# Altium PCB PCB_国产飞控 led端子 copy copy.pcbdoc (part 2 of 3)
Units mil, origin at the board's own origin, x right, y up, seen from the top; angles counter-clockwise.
Board outline 3467.18 x 2997.13 mil, 4 copper layers (Top Layer, Inner1, Inner2, Bottom Layer), stack 2.757 mil thick; 107 components, 163 nets, 527 pads, 148 vias.
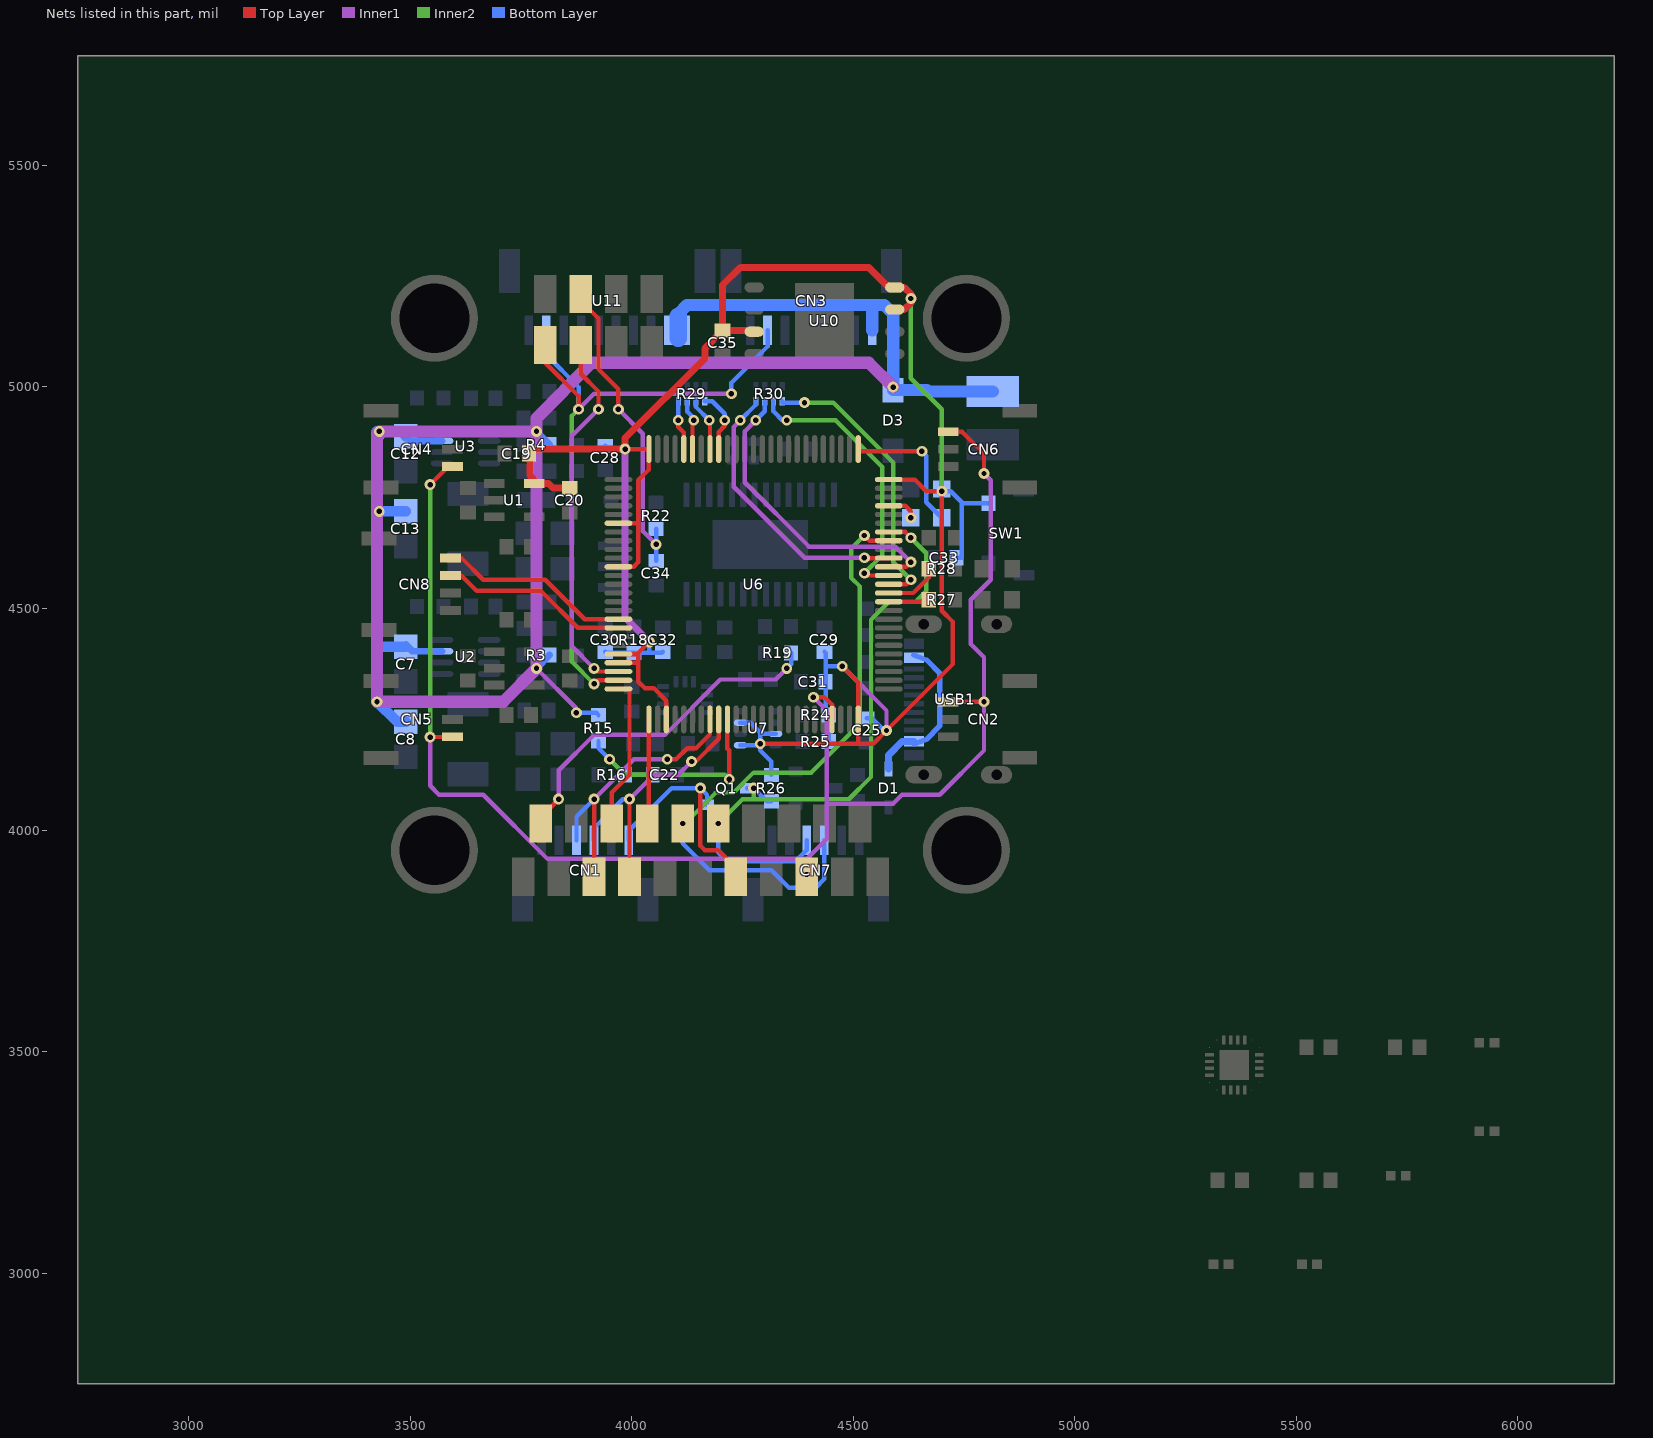
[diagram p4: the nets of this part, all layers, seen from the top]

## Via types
v1: diameter 24.41, hole 12.2, Top Layer to Bottom Layer, 148 vias

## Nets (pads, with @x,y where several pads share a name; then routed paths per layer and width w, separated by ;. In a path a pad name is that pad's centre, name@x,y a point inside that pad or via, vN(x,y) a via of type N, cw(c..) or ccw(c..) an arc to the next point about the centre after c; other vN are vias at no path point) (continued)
LED: CN2.3 CN4.3 CN5.3 CN6.3 pad.5@4395,3894.63 U6.47 | length 3563.7
  Top Layer w10: v1(3545,4209.63) CN5.3@3595.7,4210.23 ; v1(3545,4779.63) 3585.6,4820.23 CN4.3@3595.7,4820.23 ; pad.5@4395,3894.63 v1(4395,3899.63) ; v1(4410,4299.63) 4435,4299.63 4452.2,4282.43 U6.47@4452.17,4249.52 ; CN2.3@4714.29,4289 v1(4795,4289.63) ; CN6.3@4714.29,4899 4745.6,4899.03 4795,4849.63 v1(4795,4804.63)
  Inner1 w10: v1(3545,4209.63) 3545,4099.63 3565,4079.63 3665,4079.63 3810,3934.63 4395,3934.63 ; v1(4410,4299.63) 4440,4269.63 4440,3979.63 4395,3934.63 ; 4440,4059.63 4590,4059.63 4610,4079.63 4695,4079.63 4795,4179.63 v1(4795,4289.63) 4795,4389.63 4765,4419.63 4765,4519.63 4810,4564.63 4810,4789.63 v1(4795,4804.63) ; 4395,3934.63 v1(4395,3899.63) 4395,3934.63
  Inner2 w10: v1(3545,4209.63) v1(3545,4779.63)
LED1: R27.2 U6.61 | length 92
  Top Layer w10: U6.61@4580.1,4515.23 4665.9,4515.23 R27.2@4670.34,4519.63
LED2: R28.2 U6.62 | length 124.4
  Top Layer w10: U6.62@4580.11,4534.94 4635.3,4534.93 4670.3,4569.93 R28.2@4670.34,4589.63
MOTOR1: R29.4 U6.92 | length 142.7
  Top Layer w10: U6.92@4196.26,4859.74 4196.3,4898.33 4210,4912.13 v1(4210,4924.63)
  Bottom Layer w10: R29.4@4164.53,4967.8 4181.8,4967.83 4210,4939.63 v1(4210,4924.63)
MOTOR2: R29.3 U6.93 | length 122.2
  Top Layer w10: v1(4175,4924.63) 4176.6,4924.63 U6.93@4176.57,4859.74
  Bottom Layer w10: R29.3@4144.84,4967.8 4144.8,4954.83 v1(4175,4924.63)
MOTOR3: R29.2 U6.95 | length 117
  Top Layer w10: U6.95@4137.2,4859.74 4137.2,4924.63 v1(4140,4924.63)
  Bottom Layer w10: R29.2@4125.16,4967.8 4125.2,4944.43 4140,4929.63 v1(4140,4924.63)
MOTOR4: R29.1 U6.96 | length 113.5
  Top Layer w10: v1(4105,4924.63) 4105,4909.63 4117.5,4897.13 U6.96@4117.52,4859.74
  Bottom Layer w10: v1(4105,4924.63) 4105,4967.33 R29.1@4105.47,4967.8
OSD_IN_CAM: C34.2 pad.5@3885,5209.63 R22.2 | length 708.1
  Top Layer w10: pad.5@3885,5209.63 3885,5194.63 3925,5154.63 3925,5039.63 3970,4994.63 v1(3970,4949.63)
  Inner1 w10: v1(3970,4949.63) 4025,4894.63 4025,4674.63 v1(4055,4644.63)
  Bottom Layer w10: C34.2@4055,4607.19 v1(4055,4644.63) R22.2@4055,4679.93
OSD_OUT_VTX: pad.5@3795,4014.63 R19.2 | length 785.9
  Top Layer w10: pad.5@3795,4014.63 3795,4029.63 v1(3835,4069.63)
  Inner1 w10: v1(3835,4069.63) 3835,4134.63 3915,4214.63 4075,4214.63 4200,4339.63 4325,4339.63 v1(4350,4364.63)
  Bottom Layer w10: v1(4350,4364.63) 4359.7,4374.33 R19.2@4359.66,4399.63
Q2_1: 
R1_1: 
R1_2: 
R3_1: 
R7_1: 
R7_2: 
R8_1: 
R11_2: 
R12_2: 
R13_2: 
R27_1: 
R28_1: 
R29_5: 
R29_6: 
R29_7: 
R29_8: 
R30_5: 
R30_6: 
R30_7: 
R30_8: 
S$147824: 
S$244950: 
S$244954: 
S$288220: 
S$288224: 
S$288228: 
S$288280: 
S$288284: 
S$288288: 
S$288292: 
SBUS: CN1.1 pad.5@4235,3894.63 Q1.1 | length 517.4
  Top Layer w10: v1(4155,4094.63) 4155,3964.63 4165,3954.63 4195,3954.63 4235,3914.63 pad.5@4235,3894.63
  Bottom Layer w10: CN1.1@3993.4,3976.53 3993.4,3998.03 4090,4094.63 v1(4155,4094.63) 4169.8,4079.83 Q1.1@4169.8,4057.23
SERVO1: R30.4 U6.63 | length 645.2
  Top Layer w10: U6.63@4580.11,4554.63 4620,4554.63 v1(4630,4564.63)
  Inner2 w10: v1(4390,4964.63) 4455,4964.63 4590,4829.63 4590,4604.63 v1(4630,4564.63)
  Bottom Layer w10: R30.4@4339.53,4967.8 4339.5,4964.63 v1(4390,4964.63)
SERVO2: R30.3 U6.64 | length 633.9
  Top Layer w10: v1(4525,4579.63) 4530.3,4574.33 U6.64@4580.11,4574.31
  Inner2 w10: v1(4350,4924.63) 4460,4924.63 4565,4819.63 4565,4619.63 v1(4525,4579.63)
  Bottom Layer w10: R30.3@4319.84,4967.8 4319.8,4944.83 4340,4924.63 v1(4350,4924.63)
SERVO3: R30.2 U6.65 | length 705.8
  Top Layer w10: U6.65@4580.11,4594 4619.4,4594.03 v1(4630,4604.63)
  Inner1 w10: v1(4280,4924.63) 4255,4899.63 4255,4784.63 4400,4639.63 4595,4639.63 v1(4630,4604.63)
  Bottom Layer w10: v1(4280,4924.63) 4300.2,4944.83 R30.2@4300.16,4967.8
SERVO4: R30.1 U6.66 | length 630.9
  Top Layer w10: v1(4525,4614.63) 4525.9,4613.73 U6.66@4580.11,4613.69
  Inner1 w10: v1(4245,4924.63) 4230,4909.63 4230,4774.63 4390,4614.63 v1(4525,4614.63)
  Bottom Layer w10: v1(4245,4924.63) 4280.5,4960.13 R30.1@4280.47,4967.8
SWDCLK: pad.5@4700,4704.63 U6.76 | length 317.5
  Top Layer w10: U6.76@4511.22,4859.74 4511.2,4854.63 v1(4655,4854.63)
  Bottom Layer w10: v1(4655,4854.63) 4665,4844.63 4665,4739.63 pad.5@4700,4704.63
SWDIO: pad.5@4630,4704.63 U6.72 | length 70
  Top Layer w10: U6.72@4580.11,4731.8 4617.8,4731.83 4630,4719.63 v1(4630,4704.63)
U3_1: 
U3_2: 
U3_3: 
U3_4: 
U3_6: 
U3_8: 
U6_14: 
U6_37: 
U9_5: 
U9_6: 
U9_19: 
U9_22: 
UART1_RX: CN7.4 pad.5@4195,4014.63 Q1.3 R26.1 U6.69 | length 1483
  Top Layer w10: U6.69@4580.11,4672.74 4616.9,4672.73 v1(4630,4659.63)
  Inner2 w10: v1(4195,4014.63) 4250,4069.63 4490,4069.63 4540,4119.63 4540,4474.63 4580,4514.63 4640,4514.63 4665,4539.63 4665,4624.63 v1(4630,4659.63) ; 4275,4069.63 v1(4275,4094.63)
  Bottom Layer w10: v1(4195,4014.63) 4195,3949.63 4215,3929.63 4370,3929.63 4395.3,3954.93 CN7.4@4395.3,3976.53 ; Q1.3@4260.2,4094.63 v1(4275,4094.63) 4304.7,4064.93 R26.1@4315,4064.93
UART1_TX: CN7.3 pad.5@4115,4014.63 U6.68 | length 1500.3
  Top Layer w10: v1(4525,4664.63) 4536.6,4653.03 U6.68@4580.1,4653.03
  Inner2 w10: v1(4115,4014.63) 4120,4014.63 4190,4084.63 4230,4084.63 4275,4129.63 4405,4129.63 4515,4239.63 4515,4549.63 4495,4569.63 4495,4634.63 v1(4525,4664.63)
  Bottom Layer w10: v1(4115,4014.63) 4115,3969.63 4175,3909.63 4315,3909.63 4355,3869.63 4415,3869.63 4434.7,3889.33 CN7.3@4434.7,3976.53
UART2_RX: pad.5@4035,4014.63 U6.26 | length 238.7
  Top Layer w10: pad.5@4035,4014.63 4038.8,4014.63 U6.26@4038.78,4249.52
UART2_TX: pad.5@3955,4014.63 U6.25 | length 345.5
  Top Layer w10: pad.5@3955,4014.63 3955,4084.63 3995,4124.63 3995,4318.43 U6.25@3969.89,4318.41
UART3_RX: CN1.3 pad.5@3995,3894.63 U6.34 | length 611.5
  Top Layer w10: pad.5@3995,3894.63 3995,3954.63 v1(3995,4069.63) ; v1(4135,4154.63) 4145,4154.63 4196.3,4205.93 U6.34@4196.26,4249.52
  Inner1 w10: v1(3995,4069.63) 4050,4124.63 4105,4124.63 v1(4135,4154.63)
  Bottom Layer w10: CN1.3@3914.7,3976.53 3914.7,4004.33 3980,4069.63 v1(3995,4069.63)
UART3_TX: CN1.4 pad.5@3915,3894.63 U6.33 | length 640.2
  Top Layer w10: pad.5@3915,3894.63 3915,3959.63 v1(3915,4069.63) ; v1(4080,4159.63) 4100,4159.63 4125,4184.63 4145,4184.63 4176.6,4216.23 U6.33@4176.57,4249.52
  Inner1 w10: v1(3915,4069.63) 4005,4159.63 v1(4080,4159.63)
  Bottom Layer w10: CN1.4@3875.3,3976.53 3875.3,4029.93 v1(3915,4069.63)
UART4_RX: CN3.2 pad.5@3805,5094.63 U6.24 U11.2 | length 1626.1
  Top Layer w10: pad.5@3805,5094.63 3805,5054.63 3880,4979.63 v1(3880,4949.63) ; v1(3915,4329.63) 3923.5,4338.13 U6.24@3969.89,4338.09
  Inner1 w10: v1(3880,4949.63) 3915,4984.63 v1(4225,4984.63)
  Inner2 w10: v1(3880,4949.63) 3865,4934.63 3865,4379.63 v1(3915,4329.63)
  Bottom Layer w10: U11.2@3807.19,5127.7 3807.2,5072.43 3880,4999.63 v1(3880,4949.63) ; v1(4225,4984.63) 4225,5009.63 4306.6,5091.23 CN3.2@4306.59,5127.7
UART4_TX: pad.5@3885,5094.63 U6.23 | length 849.9
  Top Layer w10: pad.5@3885,5094.63 3885,5029.63 3925,4989.63 v1(3925,4949.63) ; v1(3915,4364.63) 3921.9,4357.73 U6.23@3969.9,4357.73
  Inner1 w10: v1(3915,4364.63) 3865,4414.63 3865,4889.63 v1(3925,4949.63)
UART8_RX: CN8.2 U6.18 | length 428.1
  Top Layer w10: CN8.2@3590.71,4574.32 3615.3,4574.33 3650,4539.63 3795,4539.63 3878,4456.63 U6.18@3970,4456.63
UART8_TX: CN8.1 U6.17 | length 436.3
  Top Layer w10: CN8.1@3590.71,4613.69 3615.9,4613.73 3665,4564.63 3805,4564.63 3893.7,4475.93 U6.17@3969.89,4475.89
VBAT: C7.2 C8.2 C12.2 C13.2 CN3.8 D3.1 pad.5@4815,4989.63 R3.2 R4.2 R15.2 U2.7 U3.7 U11.9 U11.10 | length 5190.9
  Inner1 w10: v1(3785,4364.63) 3875,4274.63 v1(3875,4264.63)
  Inner1 w27.56: v1(4590,4999.63) 4535,5054.63 3909,5054.63 3784.8,4929.13 v1(3785,4899.63) ; v1(3785,4899.63) v1(3430,4899.63) 3425,4894.63 v1(3425,4289.63) 3710,4289.63 v1(3785,4364.63) v1(3785,4899.63)
  Bottom Layer w10: v1(3875,4264.63) 3919.7,4264.63 R15.2@3925,4259.3
  Bottom Layer w15.75: C7.2@3490,4419.03 3505.6,4403.43 U2.7@3572,4403.43 ; C12.2@3490,4889 3500.6,4878.43 U3.7@3572,4878.43 ; v1(3785,4364.63) R3.2@3814.66,4394.63 ; v1(3785,4899.63) R4.2@3814.66,4869.63
  Bottom Layer w23.62: v1(3430,4719.03) C13.2@3490,4719 ; v1@3430,4889.03 v1(3430,4899.63) ; 3435,4414.03 C7.2@3490,4414 ; C8.2@3490,4244 3470.6,4244.03 v1(3425,4289.63) 3425,4899.63 3490,4899.63 C12.2@3490,4889
  Bottom Layer w27.56: 4105,5127.73 4105,5164.63 4125,5184.63 4542.8,5184.63 ; CN3.8@4542.81,5127.7 4542.8,5184.63 ; pad.5@4815,4989.63 4670,4989.63 4666.7,4992.93 D3.1@4589.99,4992.94 4590,5164.63 4570,5184.63 4542.8,5184.63
  Bottom Layer w39.37: 4105,5109.32 4105,5159.94
VBAT_ADC: C22.2 R15.1 R16.2 U6.35 | length 594.9
  Top Layer w10: U6.35@4215.94,4249.52 4215.9,4183.73 4220,4179.63 v1(4220,4114.63)
  Inner2 w10: v1(3950,4159.63) 3985,4124.63 4210,4124.63 v1(4220,4114.63)
  Bottom Layer w10: R15.1@3925,4199.93 3925,4184.33 R16.2@3984.66,4124.63 C22.2@4047.45,4124.63 ; v1(3950,4159.63) 3950,4159.33 v1@3954.7,4154.63
VBUS: D1.1 USB1.A4 USB1.A9 USB1.B4 USB1.B9 | length 366
  Bottom Layer w11.81: USB1.A9@4636.59,4194.24 4665,4204.63 4695,4234.63 4695,4354.63 4666.4,4383.23 USB1.A4@4636.59,4395.02
  Bottom Layer w15.75: D1.1@4580,4137.84 4580,4169.63 4610,4199.63 USB1.A9@4636.6,4199.63
VDD: C19.2 C20.2 C25.2 C28.2 C29.2 C30.2 C31.2 C32.2 C33.2 C35.1 pad.5@4700,4769.63 R18.2 R24.2 R25.2 R26.2 SW1.2 U1.5 U6.6 U6.11 U6.21 U6.22 U6.28 U6.50 U6.75 U6.100 U7.2 U7.6 U7.8 U10.3 U10.7 U10.8 | length 5516.6
  Top Layer w10: U6.22@3969.9,4377.43 4015,4377.43 ; U6.21@3969.9,4397.13 4012.5,4397.13 v1(4040,4424.63) ; U6.11@3969.89,4594 4004.4,4594.03 4015,4604.63 4015,4692.43 4015,4789.63 4038.8,4813.43 U6.100@4038.78,4859.74 3985.1,4859.73 v1(3985,4859.63) ; 4015,4399.63 4015,4377.43 ; U6.28@4078.1,4249.53 4078.1,4291.53 4050,4319.63 4030,4319.63 4015,4334.63 4015,4377.43 ; v1(4290,4194.63) 4545,4194.63 v1(4575,4224.63) 4725,4374.63 4725,4469.63 4700,4494.63 v1(4700,4764.63) 4665,4764.63 4638.8,4790.83 U6.75@4580.11,4790.85 ; v1(4475,4369.63) 4511.2,4333.43 U6.50@4511.22,4249.52 4511.2,4199.63
  Top Layer w10.08: U6.6@3969.89,4692.43 4015,4692.43
  Top Layer w15.75: C19.2@3767.86,4849.63 3767.9,4859.63 v1(3985,4859.63) 3985,4884.63 4165,5064.63 4165,5087.23 C35.1@4205,5127.19 ; C19.2@3770,4849.63 3770,4799.63 3787.6,4782.03 3796.2,4782.03 3812.6,4782.03 3822.4,4772.23 C20.2@3850,4772.23 ; U10.3@4276.23,5124.63 4273.6,5127.23 C35.1@4205,5127.19 ; U10.7@4593.77,5174.63 4615,5174.63 4630,5189.63 v1(4630,5199.63) 4630,5209.63 4615,5224.63 U10.8@4593.77,5224.63 4580,5224.63 4535,5269.63 4245,5269.63 4205,5229.63 C35.1@4205,5127.19
  Inner1 w10: v1(4475,4369.63) 4575,4269.63 v1(4575,4224.63)
  Inner1 w15.75: v1(3985,4859.63) 3985,4479.63 v1(4040,4424.63)
  Inner2 w10: v1(4630,5199.63) 4630,5019.63 4700,4949.63 v1(4700,4764.63)
  Bottom Layer w10: C30.2@3940,4402.03 3942.1,4399.93 4005,4399.93 4067.9,4399.93 C32.2@4070,4402.03 ; C28.2@3940,4867.19 3947.6,4859.63 v1(3985,4859.63) ; 4040,4399.97 v1(4040,4424.63) ; U7.8@4245.29,4191.24 4286.6,4191.23 v1(4290,4194.63) ; U7.6@4245.29,4242.43 4267.2,4242.43 4290,4219.63 v1(4290,4194.63) ; 4290,4216.83 U7.2@4324.7,4216.84 ; R26.2@4315,4124.3 4315,4154.63 4290,4179.63 v1(4290,4194.63) ; C29.2@4435,4402.03 4437.6,4399.53 4437.6,4369.73 ; R25.2@4444.66,4199.63 R24.2@4444.66,4259.63 4437.6,4266.73 C31.2@4437.56,4334.63 4437.6,4369.73 ; v1(4475,4369.63) 4437.7,4369.63 4437.6,4369.73 ; C25.2@4530,4252.19 4542.4,4252.23 4570,4224.63 v1(4575,4224.63) ; pad.5@4700,4769.63 v1(4700,4764.63) ; C33.2@4732.56,4614.63 4745,4614.63 4745,4739.63 ; SW1.2@4805.11,4737.81 4746.8,4737.83 4745,4739.63 ; v1(4700,4764.63) 4720,4764.63 ; v1(4700,4764.63) 4720,4764.63 ; 4720,4764.63 4745,4739.63
pads on no net: CN3.1 SDO1.2 SDO1.3 SDO1.10 SDO1.11 SW1.3 SW1.4 U1.4 U6.1 U6.2 U6.3 U6.4 U6.5 U6.7 U6.8 U6.9 U6.19 U6.38 U6.39 U6.40 U6.41 U6.42 U6.43 U6.44 U6.45 U6.46 U6.49 U6.51 U6.52 U6.53 U6.54 U6.55 U6.56 U6.57 U6.58 U6.59 U6.67 U6.73 U6.81 U6.83 U6.88 U6.89 U6.90 U6.91 U6.97 U6.98 U9.1 U9.2 U9.7 U9.12 U9.13 U9.14 U9.15 U9.16 U9.17 U9.18 U9.27 U9.28 U9.29 U12.4 USB1.A5 USB1.A8 USB1.B5 USB1.B8

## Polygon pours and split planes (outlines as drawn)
GND on Bottom Layer (solid, pour order 14): 3007.5,5482.13 3007.5,3587.13 3032.5,3562.13 5152.5,3562.13 5152.5,5462.13 5132.5,5482.13 5267.5,5482.13 5282.5,5497.13
GND on Inner2 (solid): 3025,5469.63 3025,3559.63 3020,3554.63 5150,3554.63 5150,5434.63 5095,5489.63
GND on Inner1 (solid): 3000,5492.13 3000,3597.13 3040,3557.13 5085,3557.13 5145,3617.13 5145,5467.13 5150,5472.13
GND on Top Layer (solid, pour order 4): 3030,5457.13 3030,3557.13 3040,3547.13 5110,3547.13 5130,3567.13 5130,5447.13 5125,5452.13

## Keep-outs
Board Outline Layer:
  region: 3534.12,5133.75 3334.12,5333.75 cw(c3355.14,5354.49) 3375.88,5375.51 3575.88,5175.51 cw(c3554.86,5154.77)
  region: 3534.12,5133.75 3334.12,5333.75 cw(c3355.14,5354.49) 3375.88,5375.51 3575.88,5175.51 cw(c3554.86,5154.77)
  region: 4734.12,5175.51 4934.12,5375.51 cw(c4954.86,5354.49) 4975.88,5333.75 4775.88,5133.75 cw(c4755.14,5154.77)
  region: 4734.12,5175.51 4934.12,5375.51 cw(c4954.86,5354.49) 4975.88,5333.75 4775.88,5133.75 cw(c4755.14,5154.77)
  region: 4775.88,3975.51 4970.88,3780.51 cw(c4949.86,3759.77) 4929.12,3738.75 4734.12,3933.75 cw(c4755.14,3954.49)
  region: 4775.88,3975.51 4970.88,3780.51 cw(c4949.86,3759.77) 4929.12,3738.75 4734.12,3933.75 cw(c4755.14,3954.49)
  region: 3575.88,3933.75 3380.88,3738.75 cw(c3360.14,3759.77) 3339.12,3780.51 3534.12,3975.51 cw(c3554.86,3954.49)
  region: 3575.88,3933.75 3380.88,3738.75 cw(c3360.14,3759.77) 3339.12,3780.51 3534.12,3975.51 cw(c3554.86,3954.49)
  lines w0.1: 3334.12,5333.75 3534.12,5133.75 ccw(c3554.86,5154.77) 3575.88,5175.51 3375.88,5375.51 ccw(c3355.14,5354.49) 3334.12,5333.75 ; 3339.12,3780.51 ccw(c3360.14,3759.77) 3380.88,3738.75 3575.88,3933.75 ccw(c3554.86,3954.49) 3534.12,3975.51 3339.12,3780.51 ; 4734.12,3933.75 4929.12,3738.75 ccw(c4949.86,3759.77) 4970.88,3780.51 4775.88,3975.51 ccw(c4755.14,3954.49) 4734.12,3933.75 ; 4734.12,5175.51 4934.12,5375.51 cw(c4954.86,5354.49) 4975.88,5333.75 4775.88,5133.75 cw(c4755.14,5154.77) 4734.12,5175.51
  lines w10: 3397.13,3954.24 3397.13,5155.02 cw(c3554.61,5155.02) 3554.61,5312.5 4755.39,5312.5 cw(c4755.39,5155.02) 4912.87,5155.02 4912.87,3954.24 cw(c4755.39,3954.24) 4755.39,3796.76 3554.61,3796.76 cw(c3554.61,3954.24) 3397.13,3954.24

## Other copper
Top Layer:
  region net BOX_MOSI: 4415.85,4996.56 4434.15,4996.56 4430,4988.01 4420,4988.01
  region net BOX_MOSI: 4508.07,4995.48 4508.07,5013.78 4516.62,5009.63 4516.62,4999.63
  region net AT_CS: 4307.18,4803.87 4294.24,4816.81 4303.21,4819.92 4310.29,4812.84
  region net AT_SCK: 4415.76,4816.81 4402.82,4803.87 4399.71,4812.84 4406.79,4819.92
  region net AT_MISO: 4378.15,4816.69 4368.26,4801.29 4363.25,4809.31 4368.79,4817.92
  region net AT_MOSI: 4323.12,4814.71 4340.86,4810.2 4339.1,4819.46 4329.1,4822.01
  region net BOOT0: 4766.93,4650.48 4766.93,4668.78 4758.38,4664.63 4758.38,4654.63
  region net BOOT0: 4765.85,4667.7 4784.15,4667.7 4780.04,4676.25 4769.96,4676.25
  region net MOTOR4: 4095.85,4916.56 4114.15,4916.56 4110,4909.63 4100,4909.63
  region net MOTOR3: 4147.66,4915.13 4129.62,4918.22 4132.2,4909.11 4142.2,4907.4
  region net MOTOR2: 4184.89,4917.48 4166.67,4915.71 4171.6,4907.61 4181.6,4908.57
  region net MOTOR1: 4200.85,4916.56 4219.15,4916.56 4215,4912.13 4205,4912.13
  region net GYRO_MOSI: 4190.85,4356.56 4209.15,4356.56 4205,4348.01 4195,4348.01
  region net GYRO_SCK: 4125.26,4363.03 4107.16,4360.27 4112.5,4352.44 4122.5,4353.96
  region net GYRO_CS1: 4066.66,4337.89 4082.06,4347.78 4083.29,4338.42 4074.68,4332.88
  region net GYRO_MISO: 4170.76,4337.45 4157.82,4350.39 4154.71,4341.42 4161.79,4334.34
  region net GYRO_EXTI2: 4487.18,4428.87 4474.24,4441.81 4483.21,4444.92 4490.29,4437.84
  region net GYRO_EXTI1: 4499.84,4811.84 4481.61,4813.5 4486.5,4821.63 4496.5,4820.73
  region net D-: 4473.07,4655.48 4473.07,4673.78 4481.62,4669.63 4481.62,4659.63
  region net D+: 4499.36,4722.47 4496.6,4704.37 4505.67,4707.13 4507.19,4717.13
  region net BB: 4465.85,4086.56 4484.15,4086.56 4480,4078.01 4470,4078.01
  region net SBUS: 4145.85,4086.56 4164.15,4086.56 4160,4078.01 4150,4078.01
  region net +10V: 3735.85,4046.56 3754.15,4046.56 3752.87,4038.01 3737.13,4038.01
  region net UART3_TX: 3905.85,4061.56 3924.15,4061.56 3920,4053.01 3910,4053.01
  region net UART3_RX: 3985.85,4061.56 4004.15,4061.56 4000,4053.01 3990,4053.01
  region net I2C_SCL: 4335.85,4307.7 4354.15,4307.7 4350,4316.25 4340,4316.25
  region net I2C_SDA: 4275.85,4307.7 4294.15,4307.7 4290,4316.25 4280,4316.25
  region net I2C_SDA: 4341.93,4085.48 4341.93,4103.78 4335,4099.63 4335,4089.63
  region net I2C_SCL: 4405.76,4082.45 4392.82,4095.39 4389.71,4086.42 4396.79,4079.34
  region net BEEPER: 4480.02,4297.66 4461.83,4295.56 4466.9,4287.55 4476.9,4288.7
  region net UART3_RX: 4145.7,4148.75 4139.49,4165.98 4148.76,4165.46 4152.51,4155.06
  region net UART3_TX: 4088.07,4150.48 4088.07,4168.78 4096.62,4164.63 4096.62,4154.63
  region net U6_37: 4239.43,4288.77 4256.47,4295.46 4256.15,4286.15 4245.99,4282.17
  region net HEXT_OUT: 3912.18,4543.87 3899.24,4556.81 3906.46,4558.17 3913.54,4551.09
  region net HEXT_IN: 3885.85,4621.56 3904.15,4621.56 3900,4613.01 3890,4613.01
  region net U6_14: 3905.85,4512.7 3924.15,4512.7 3920,4521.25 3910,4521.25
  region net OSD_OUT_VTX: 3835.76,4057.45 3822.82,4070.39 3819.71,4061.42 3826.79,4054.34
  region net OSD_IN_CAM: 3960.85,4957.7 3979.15,4957.7 3975,4966.25 3965,4966.25
  region net UART4_TX: 3926.14,4369.61 3918.54,4352.95 3927.83,4352.73 3932.4,4362.73
  region net UART4_RX: 3926.62,4325.9 3917.25,4341.63 3926.3,4343.13 3932.25,4333.13
  region net UART4_TX: 3915.85,4957.7 3934.15,4957.7 3930,4966.25 3920,4966.25
  region net UART4_RX: 3870.85,4957.7 3889.15,4957.7 3885,4966.25 3875,4966.25
  region net 3V3-IMU: 3961.93,4255.48 3961.93,4273.78 3953.38,4270.54 3953.38,4258.72
  region net SERVO4: 4533.56,4623.33 4532.56,4605.05 4541.32,4608.73 4541.86,4618.73
  region net SERVO3: 4630.76,4592.45 4617.82,4605.39 4615.86,4597.56 4622.93,4590.49
  region net SERVO2: 4535.57,4585.73 4529.73,4568.38 4539.07,4569.33 4542.43,4579.33
  region net SERVO1: 4630.76,4552.45 4617.82,4565.39 4616.46,4558.17 4623.54,4551.09
  region net UART1_RX: 4630.76,4671.81 4617.82,4658.87 4614.71,4667.84 4621.79,4674.92
  region net UART1_TX: 4537.18,4665.39 4524.24,4652.45 4533.06,4649.5 4540.13,4656.57
  region net VBAT_ADC: 4210.85,4122.7 4229.15,4122.7 4225,4131.25 4215,4131.25
  region net CURRENT1: 4260.76,4176.81 4247.82,4163.87 4244.71,4172.84 4251.79,4179.92
  region net SWDCLK: 4646.93,4845.48 4646.93,4863.78 4638.38,4859.63 4638.38,4849.63
  region net SWDIO: 4620.85,4712.7 4639.15,4712.7 4635,4719.63 4625,4719.63
  region net LED: 4418.07,4290.48 4418.07,4308.78 4426.62,4304.63 4426.62,4294.63
  region net +5V: 3910.76,4672.45 3897.82,4685.39 3892.68,4678.45 3903.82,4667.31
  region net +10V: 3748.07,5170.48 3748.07,5188.78 3756.62,5187.5 3756.62,5171.76
  region net VDD: 4691.93,4755.48 4691.93,4773.78 4683.38,4769.63 4683.38,4759.63
  region net VDD: 4690.85,4756.56 4709.15,4756.56 4705,4748.01 4695,4748.01
  region net VDD: 3975.85,4867.7 3994.15,4867.7 3992.87,4876.25 3977.13,4876.25
  region net VDD: 3976.93,4850.48 3976.93,4868.78 3968.38,4867.5 3968.38,4851.76
  region net VDD: 3993.13,4850.52 3993.02,4868.83 4001.59,4864.73 4001.65,4854.73
  region net VDD: 4587.18,4223.87 4574.24,4236.81 4583.21,4239.92 4590.29,4232.84
  region net VDD: 4575.76,4212.45 4562.82,4225.39 4559.71,4216.42 4566.79,4209.34
  region net VDD: 4635.88,5210.33 4618.65,5204.12 4616.18,5212.31 4632.55,5218.21
  region net VDD: 4635.88,5188.93 4618.65,5195.14 4616.18,5186.95 4632.55,5181.05
  region net LED: 4787,4280.42 4786.86,4298.72 4778.35,4294.51 4778.42,4284.51
  region net LED: 3557.18,4778.87 3544.24,4791.81 3553.21,4794.92 3560.29,4787.84
  region net LED: 3553.18,4200.57 3552.96,4218.88 3561.56,4214.83 3561.67,4204.83
  region net LED: 4785.85,4812.7 4804.15,4812.7 4800,4821.25 4790,4821.25
  region net +5V: 4035.85,5271.56 4054.15,5271.56 4052.87,5263.01 4037.13,5263.01
  region net +5V: 4756.93,4240.48 4756.93,4258.78 4748.38,4254.63 4748.38,4244.63
  region net +5V: 4565.85,4006.56 4584.15,4006.56 4582.87,3998.01 4567.13,3998.01
  region net +5V: 4566.93,4005.48 4566.93,4023.78 4558.38,4022.5 4558.38,4006.76
  region net +5V: 3665.76,4476.81 3652.82,4463.87 3649.7,4472.83 3656.8,4479.93
  region net +5V: 3655.85,4456.56 3674.15,4456.56 3672.87,4448.01 3657.13,4448.01
  region net VDD: 4298.07,4185.48 4298.07,4203.78 4306.62,4199.63 4306.62,4189.63
  region net VDD: 4487.18,4370.39 4474.24,4357.45 4483.21,4354.34 4490.29,4361.42
  region net +5V: 3734.58,4707.99 3721.64,4695.05 3728.58,4689.91 3739.72,4701.05
  region net +5V: 3734.57,4706.36 3721.74,4719.42 3728.73,4724.49 3739.77,4713.26
  region net +5V: 3714.33,4698.08 3714.33,4716.38 3705.78,4715.1 3705.78,4699.36
  region net +5V: 3714.33,4698.08 3714.33,4716.38 3705.78,4715.1 3705.78,4699.36
  region net VDD: 4040.76,4412.45 4027.82,4425.39 4024.71,4416.42 4031.79,4409.34
  region net I2C_SCL: 4345.85,4022.7 4364.15,4022.7 4360,4031.25 4350,4031.25
  region net I2C_SDA: 4265.85,4022.7 4284.15,4022.7 4280,4031.25 4270,4031.25
  region net +10V: 3729.41,3937.94 3764.68,3937.94 3752.87,3961.56 3737.13,3961.56
  region net UART2_RX: 4026.3,4057.94 4051.3,4057.94 4043.8,4072.94 4033.8,4072.94
  region net UART2_TX: 3942.5,4057.94 3967.5,4057.94 3960,4072.94 3950,4072.94
  region net +5V: 4174.69,3851.32 4135.31,3851.32 4147.13,3829.63 4162.87,3829.63
  region net SBUS: 4209.41,3926.55 4231.66,3937.94 4211.99,3944.72 4202.63,3939.93
  region net +5V: 4334.69,3851.32 4295.31,3851.32 4307.13,3829.63 4322.87,3829.63
  region net +5V: 4540.59,4034.32 4540.59,3994.95 4564.21,4006.76 4564.21,4022.5
  region net BB: 4462.5,3937.94 4487.5,3937.94 4480,3952.94 4470,3952.94
  region net I2C_SCL: 4355.81,4057.94 4380.59,4057.94 4390.38,4072.94 4376.24,4072.94
  region net I2C_SDA: 4278.34,4057.94 4300.59,4046.55 4307.37,4059.93 4298.01,4064.72
  region net UART3_TX: 3902.5,3937.94 3927.5,3937.94 3920,3952.94 3910,3952.94
  region net UART3_RX: 3982.5,3937.94 4007.5,3937.94 4000,3952.94 3990,3952.94
  region net +5V: 3855.32,4057.94 3894.68,4057.94 3882.87,4081.56 3867.13,4081.56
  region net +5V: 3894.68,3971.32 3855.32,3971.32 3867.13,3947.7 3882.87,3947.7
  region net OSD_OUT_VTX: 3810.43,4057.94 3820.59,4035.1 3827.93,4055.49 3823.58,4065.28
  region net +10V: 3779.41,5166.32 3779.41,5199.31 3755.79,5187.5 3755.79,5171.76
  region net OSD_IN_CAM: 3910.59,5189.16 3900.43,5166.32 3913.58,5158.98 3917.93,5168.77
  region net +5V: 4064.68,5166.32 4025.32,5166.32 4037.13,5142.7 4052.87,5142.7
  region net +5V: 4025.32,5252.94 4064.68,5252.94 4052.87,5276.56 4037.13,5276.56
  region net +5V: 4025.32,5137.94 4064.68,5137.94 4052.87,5161.56 4037.13,5161.56
  region net UART4_TX: 3897.5,5051.32 3872.5,5051.32 3880,5036.32 3890,5036.32
  region net UART4_RX: 3820.81,5051.32 3795.81,5051.32 3816.24,5036.32 3830.38,5036.32
  region net +5V: 4542.05,3937.94 4580.59,3929.88 4580.57,3934.06 4565.79,3941.56
  region net +5V: 4566.38,3851.32 4529.41,3851.32 4519.43,3835.2 4536.14,3829.63
  region net UART8_TX: 3614.3,4623.53 3614.3,4603.83 3615.94,4608.69 3615.94,4618.69
  region net UART8_RX: 3614.3,4584.13 3614.3,4564.43 3615.31,4569.32 3615.31,4579.32
  region net +5V: 3614.3,4505.43 3614.3,4485.73 3629.36,4490.56 3629.36,4500.6
  region net LED: 4737.91,4298.84 4737.91,4279.16 4752.91,4284.32 4752.91,4294.32
  region net +5V: 4737.91,4259.47 4737.91,4239.79 4752.91,4244.63 4752.91,4254.63
  region net LED: 3595.95,4810.42 3572.09,4817.89 3563.24,4804.94 3574.01,4801.57
  region net +5V: 3619.33,4869.47 3618.68,4849.79 3633.22,4835.54 3633.67,4849.23
  region net LED: 3572.09,4200.42 3572.09,4220.1 3557.09,4214.77 3557.09,4204.77
  region net +5V: 3602.98,4259.47 3619.33,4240.56 3623.28,4255.84 3616.46,4263.17
  region net LED: 4737.91,4908.84 4737.91,4889.16 4745.6,4894.03 4745.6,4904.03
  region net BOOT0: 4745.53,4647.13 4745.53,4672.13 4760.53,4664.63 4760.53,4654.63
  region net 3V3-IMU: 3776.19,4390.22 3799.22,4413.84 3778.17,4421.2 3767.1,4409.99
  region net 3V3-IMU: 3815.56,4413.84 3815.56,4390.22 3839.19,4394.16 3839.19,4409.9
  region net +5V: 3713.2,4315.42 3674.53,4315.42 3706.36,4292.13 3723.07,4297.7
  region net +5V: 3713.2,4339.04 3713.2,4315.42 3717.6,4319.36 3717.6,4335.1
  region net +5V: 3713.2,4413.84 3713.2,4390.22 3722.6,4394.16 3722.6,4409.9
  region net +5V: 3673.83,4390.22 3673.83,4413.84 3652.4,4409.9 3652.4,4394.16
  region net +5V: 3673.83,4413.84 3713.19,4413.84 3701.38,4416.13 3685.63,4416.13
  region net VDD: 3776.5,4770.22 3802.51,4793.84 3777.62,4803.15 3765.95,4792.55
  region net VDD: 3815.87,4793.84 3810.73,4770.22 3816.83,4766.66 3824.39,4781.37
  region net +5V: 3713.5,4719.04 3713.5,4695.42 3722.6,4699.36 3722.6,4715.1
  region net +5V: 3674.13,4695.42 3674.13,4719.04 3652.4,4715.1 3652.4,4699.36
  region net +5V: 3713.5,4719.04 3713.5,4695.42 3722.4,4699.36 3722.4,4715.1
  region net +5V: 3674.13,4793.84 3694.49,4793.84 3674.06,4808.84 3659.92,4808.84
  region net +5V: 3713.5,4793.84 3713.5,4770.22 3717.6,4774.16 3717.6,4789.9
  region net +5V: 3646.73,4407.94 3647.72,4376.44 3652.74,4391.23 3646.83,4407.6
  region net +5V: 3701.69,4247.13 3701.69,4272.13 3686.69,4264.63 3686.69,4254.63
  region net +5V: 3733.19,4241.91 3701.69,4241.91 3707.13,4218.29 3722.87,4218.29
  region net +5V: 3701.69,4277.35 3733.19,4277.35 3725.37,4292.13 3709.63,4292.13
  region net 3V3-IMU: 3788.31,4456.91 3756.81,4456.91 3764.73,4433.29 3780.47,4433.29
  region net 3V3-IMU: 3877.72,4392.09 3852.68,4376.44 3874.62,4369.26 3884.9,4375.68
  region net +5V: 3648.02,4732.82 3646.46,4701.32 3646.83,4701.66 3652.93,4717.84
  region net +5V: 3756.51,4657.35 3788,4657.35 3759.8,4680.97 3737.53,4680.97
  region net +5V: 3788,4657.35 3788,4621.91 3811.62,4631.76 3811.62,4647.5
  region net VDD: 3842.59,4756.44 3842.59,4787.94 3822.4,4780.1 3822.4,4764.36
  region net LED1: 4654.47,4502.73 4654.47,4527.73 4639.47,4520.23 4639.47,4510.23
  region net R27_1: 4745.53,4507.13 4745.53,4532.13 4760.53,4524.63 4760.53,4514.63
  region net LED2: 4682.8,4572.62 4657.8,4572.62 4665.3,4569.93 4675.3,4569.93
  region net R28_1: 4745.53,4577.13 4745.53,4602.13 4760.53,4594.63 4760.53,4584.63
  region net R27_1: 4773.82,4507.13 4773.82,4532.13 4758.82,4524.63 4758.82,4514.63
  region net R28_1: 4773.82,4577.13 4773.82,4602.13 4758.82,4594.63 4758.82,4584.63
  region net VDD: 3783.61,4831.91 3752.12,4831.91 3762.13,4808.29 3777.87,4808.29
  region net VDD: 4219.46,5111.44 4187.28,5134.12 4178.23,5111.6 4191.3,5102.39
  region net VDD: 4187.28,5142.94 4222.72,5142.94 4212.87,5166.56 4197.13,5166.56
  region net VDD: 4222.72,5142.94 4222.72,5111.44 4246.34,5119.36 4246.34,5135.1
  region net VDD: 4044.68,4834.16 4032.87,4834.14 4033.8,4819.14 4043.8,4819.16
  region net VDD: 4032.87,4847.23 4032.87,4872.23 4017.87,4864.73 4017.87,4854.73
  region net MOTOR4: 4123.43,4885.34 4111.61,4885.32 4112.5,4897.12 4122.5,4897.14
  region net MOTOR3: 4143.11,4885.33 4131.29,4885.33 4132.2,4900.33 4142.2,4900.33
  region net BOOT0: 4162.8,4834.15 4150.98,4834.15 4151.86,4819.03 4161.94,4819.03
  region net MOTOR2: 4182.48,4885.32 4170.66,4885.34 4171.6,4900.34 4181.6,4900.32
  region net MOTOR1: 4202.17,4885.31 4190.35,4885.35 4191.3,4898.35 4201.3,4898.32
  region net BOX_CS: 4300.6,4885.33 4288.78,4885.33 4289.7,4899.33 4299.7,4899.33
  region net AT_CS: 4320.28,4834.17 4308.46,4834.13 4309.4,4824.01 4319.4,4824.04
  region net AT_MOSI: 4339.97,4834.16 4328.15,4834.13 4329.1,4819.14 4339.1,4819.16
  region net AT_MISO: 4359.65,4834.12 4347.83,4834.18 4348.7,4825.95 4358.7,4825.91
  region net AT_SCK: 4399.02,4834.14 4387.2,4834.16 4388.1,4826.54 4398.1,4826.52
  region net BOX_MOSI: 4438.39,4885.32 4426.57,4885.34 4427.5,4900.34 4437.5,4900.32
  region net BOX_MISO: 4458.08,4885.32 4446.26,4885.34 4447.2,4900.34 4457.2,4900.32
  region net BOX_SCK: 4477.76,4885.31 4465.95,4885.35 4466.9,4900.35 4476.9,4900.31
  region net GYRO_EXTI1: 4497.45,4834.13 4485.64,4834.17 4486.5,4819.16 4496.5,4819.14
  region net SWDCLK: 4517.13,4867.13 4517.13,4842.13 4532.13,4849.63 4532.13,4859.63
  region net VDD: 4605.71,4796.76 4605.69,4784.95 4620.69,4785.83 4620.71,4795.83
  region net SWDIO: 4605.72,4725.89 4605.69,4737.71 4617.79,4736.83 4617.81,4726.83
  region net D+: 4554.53,4718.02 4554.51,4706.2 4539.51,4707.13 4539.53,4717.13
  region net D-: 4554.52,4686.52 4554.52,4698.34 4539.52,4697.43 4539.52,4687.43
  region net UART1_RX: 4605.71,4678.65 4605.7,4666.83 4616.9,4667.73 4616.9,4677.73
  region net UART1_TX: 4554.53,4647.15 4554.51,4658.97 4539.51,4658.03 4539.53,4648.03
  region net SERVO4: 4554.53,4619.6 4554.5,4607.78 4539.51,4608.73 4539.53,4618.73
  region net SERVO3: 4605.71,4588.09 4605.69,4599.91 4619.39,4599.03 4619.41,4589.03
  region net SERVO2: 4554.53,4580.22 4554.51,4568.4 4539.51,4569.33 4539.53,4579.33
  region net SERVO1: 4605.7,4548.72 4605.7,4560.54 4620,4559.63 4620,4549.63
  region net LED2: 4605.7,4540.85 4605.7,4529.03 4620.7,4529.93 4620.7,4539.93
  region net LED1: 4605.71,4521.17 4605.69,4509.35 4620.69,4510.23 4620.71,4520.23
  region net GYRO_EXTI2: 4554.54,4489.66 4554.5,4501.48 4540.89,4500.53 4540.92,4490.53
  region net VDD: 4517.13,4275.12 4505.32,4275.1 4506.2,4290.1 4516.2,4290.12
  region net VDD: 4517.13,4223.92 4505.32,4223.94 4506.2,4208.94 4516.2,4208.92
  region net BEEPER: 4477.76,4275.09 4465.95,4275.13 4466.9,4290.13 4476.9,4290.09
  region net LED: 4458.08,4275.09 4446.27,4275.13 4447.2,4282.45 4457.2,4282.41
  region net CURRENT1: 4241.54,4223.92 4229.72,4223.94 4230.6,4208.94 4240.6,4208.92
  region net VBAT_ADC: 4221.85,4223.91 4210.03,4223.94 4210.9,4208.94 4220.9,4208.92
  region net UART3_RX: 4202.17,4223.94 4190.35,4223.91 4191.3,4208.92 4201.3,4208.94
  region net UART3_TX: 4182.48,4223.95 4170.66,4223.91 4171.6,4216.21 4181.6,4216.25
  region net GYRO_MOSI: 4162.8,4275.11 4150.98,4275.11 4151.9,4290.11 4161.9,4290.11
  region net GYRO_MISO: 4143.11,4275.11 4131.29,4275.11 4132.2,4290.11 4142.2,4290.11
  region net GYRO_SCK: 4123.43,4275.12 4111.61,4275.1 4112.5,4290.1 4122.5,4290.12
  region net GYRO_CS1: 4103.74,4275.12 4091.92,4275.1 4092.8,4290.1 4102.8,4290.12
  region net VDD: 4084.05,4275.13 4072.24,4275.09 4073.1,4290.09 4083.1,4290.13
  region net UART2_RX: 4044.68,4223.94 4032.87,4223.92 4033.8,4208.92 4043.8,4208.94
  region net UART2_TX: 4000.86,4320.85 3982.5,4312.5 3990,4297.5 4000,4297.5
  region net UART4_RX: 3944.32,4343.99 3944.28,4332.18 3929.29,4333.13 3929.31,4343.13
  region net UART4_TX: 3944.32,4351.87 3944.28,4363.68 3929.28,4362.73 3929.32,4352.73
  region net VDD: 3995.49,4383.37 3995.47,4371.55 4010.47,4372.43 4010.49,4382.43
  region net VDD: 3995.49,4403.06 3995.47,4391.24 4010.47,4392.13 4010.49,4402.13
  region net UART8_RX: 3944.47,4462.1 3944.13,4450.3 3929.16,4451.63 3929.45,4461.63
  region net UART8_TX: 3944.31,4481.8 3944.28,4469.98 3929.29,4470.93 3929.31,4480.93
  region net I2C_SDA: 3995.5,4501.48 3995.47,4489.66 4010.47,4490.53 4010.49,4500.53
  region net I2C_SCL: 3995.49,4521.17 3995.47,4509.35 4010.47,4510.23 4010.49,4520.23
  region net U6_14: 3944.3,4529.03 3944.3,4540.85 3929.3,4539.93 3929.3,4529.93
  region net HEXT_OUT: 3944.3,4548.72 3944.3,4560.54 3929.3,4559.63 3929.3,4549.63
  region net HEXT_IN: 3944.31,4580.22 3944.29,4568.4 3929.29,4569.33 3929.31,4579.33
  region net VDD: 3995.5,4588.09 3995.46,4599.91 4004.38,4599.03 4004.42,4589.03
  region net VDD: 3995.48,4686.52 3995.48,4698.34 4010.6,4697.47 4010.6,4687.39
  region net BOX_CS: 4270.07,5213.18 4261.63,5235.31 4248.81,5215.51 4255.17,5207.73
  region net BOX_MISO: 4286.76,5163.18 4286.75,5186.06 4301.75,5179.63 4301.76,5169.63
  region net VDD: 4266.97,5135.99 4264.44,5113.25 4241.36,5119.36 4243.11,5135.1
  region net VDD: 4576.97,5215.06 4590.77,5236.06 4568.98,5246.79 4558.89,5234.61
  region net VDD: 4609.36,5234.87 4599.23,5214.37 4621.79,5206.71 4629.15,5221.61
  region net VDD: 4609.36,5164.37 4599.22,5184.87 4621.78,5192.54 4629.15,5177.64
  region net BOX_SCK: 4583.26,5136.06 4583.24,5113.18 4568.25,5119.63 4568.25,5129.63
  region net BOX_MOSI: 4604.29,5063.18 4583.25,5063.18 4588.8,5053.43 4598.8,5053.43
